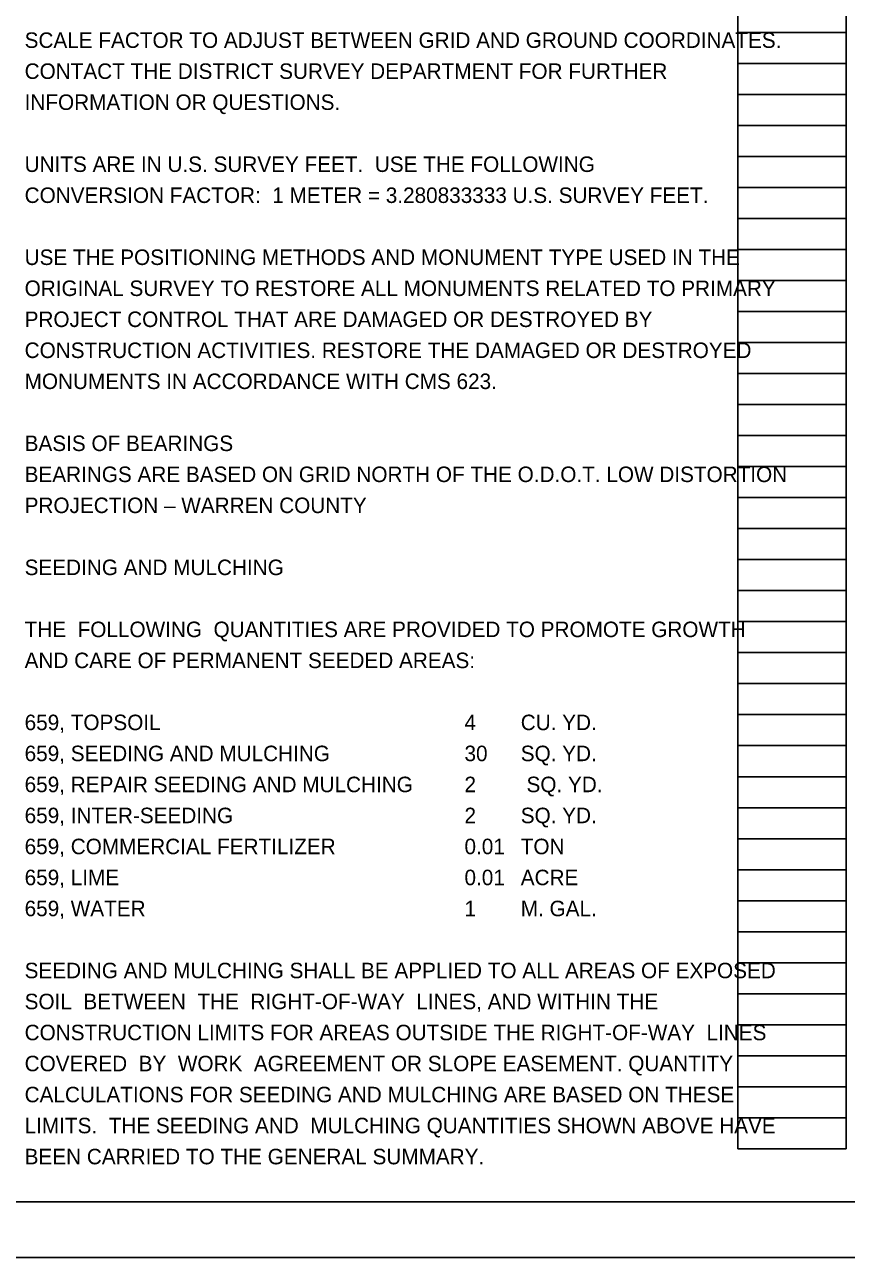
# Model space of a CAD drawing. Extents: x 0 to 34, y 0 to 22.
# Drawn here: x 17.24 to 24.66, y 0 to 11.13 of the extents above; entities that cross this region are included whole.
import ezdxf

# ---------------------------------------------------------------- set-up
doc = ezdxf.new("R2010")
doc.units = 0
for name, color, linetype in [('SH_Border', 7, 'Continuous'), ('SH_Cut_Line', 7, 'Continuous'), ('SH_Data', 7, 'Continuous'), ('SH_Text', 7, 'Continuous'), ('SN_P_Truss_Overhead', 7, 'Continuous')]:
    doc.layers.add(name, color=color, linetype=linetype)

msp = doc.modelspace()

# ---------------------------------------------------------------- linework, layer by layer
at = {"layer": 'SH_Border'}
msp.add_lwpolyline([(1.5, 21.5), (33.5, 21.5), (33.5, 0.5), (1.5, 0.5)], close=True, dxfattribs=at)
at = {"layer": 'SH_Cut_Line'}
msp.add_lwpolyline([(0, 0), (34, 0), (34, 22), (0, 22)], close=True, dxfattribs=at)
at = {"layer": 'SH_Data'}
for p, q in [((23.68, 0.98), (23.68, 21.14)), ((24.66, 0.98), (24.66, 21.14)), ((23.68, 11.06), (24.66, 11.06)), ((23.68, 10.78), (24.66, 10.78)), ((23.68, 10.5), (24.66, 10.5)), ((23.68, 10.22), (24.66, 10.22)), ((23.68, 9.94), (24.66, 9.94)), ((23.68, 9.66), (24.66, 9.66)), ((23.68, 9.38), (24.66, 9.38)), ((23.68, 9.1), (24.66, 9.1)), ((23.68, 8.82), (24.66, 8.82)), ((23.68, 8.54), (24.66, 8.54)), ((23.68, 8.26), (24.66, 8.26)), ((23.68, 7.98), (24.66, 7.98)), ((23.68, 7.7), (24.66, 7.7)), ((23.68, 7.42), (24.66, 7.42)), ((23.68, 7.14), (24.66, 7.14)), ((23.68, 6.86), (24.66, 6.86)), ((23.68, 6.58), (24.66, 6.58)), ((23.68, 6.3), (24.66, 6.3)), ((23.68, 6.02), (24.66, 6.02)), ((23.68, 5.74), (24.66, 5.74)), ((23.68, 5.46), (24.66, 5.46)), ((23.68, 5.18), (24.66, 5.18)), ((23.68, 4.9), (24.66, 4.9)), ((23.68, 4.62), (24.66, 4.62)), ((23.68, 4.34), (24.66, 4.34)), ((23.68, 4.06), (24.66, 4.06)), ((23.68, 3.78), (24.66, 3.78)), ((23.68, 3.5), (24.66, 3.5)), ((23.68, 3.22), (24.66, 3.22)), ((23.68, 2.94), (24.66, 2.94)), ((23.68, 2.66), (24.66, 2.66)), ((23.68, 2.38), (24.66, 2.38)), ((23.68, 2.1), (24.66, 2.1)), ((23.68, 1.82), (24.66, 1.82)), ((23.68, 1.54), (24.66, 1.54)), ((23.68, 1.26), (24.66, 1.26)), ((23.68, 0.98), (24.66, 0.98))]:
    msp.add_line(p, q, dxfattribs=at)

# ---------------------------------------------------------------- texts
at = {"layer": 'SH_Text'}
for s, p in [('SCALE FACTOR TO ADJUST BETWEEN GRID AND GROUND COORDINATES. ', (17.24, 10.92)), ('CONTACT THE DISTRICT SURVEY DEPARTMENT FOR FURTHER ', (17.24, 10.64)), ('INFORMATION OR QUESTIONS.', (17.24, 10.36)), ('UNITS ARE IN U.S. SURVEY FEET.  USE THE FOLLOWING', (17.24, 9.8)), ('CONVERSION FACTOR:  1 METER = 3.280833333 U.S. SURVEY FEET.', (17.24, 9.52)), ('USE THE POSITIONING METHODS AND MONUMENT TYPE USED IN THE ', (17.24, 8.96)), ('ORIGINAL SURVEY TO RESTORE ALL MONUMENTS RELATED TO PRIMARY ', (17.24, 8.68)), ('PROJECT CONTROL THAT ARE DAMAGED OR DESTROYED BY ', (17.24, 8.4)), ('CONSTRUCTION ACTIVITIES. RESTORE THE DAMAGED OR DESTROYED ', (17.24, 8.12)), ('MONUMENTS IN ACCORDANCE WITH CMS 623.', (17.24, 7.84)), ('BASIS OF BEARINGS', (17.24, 7.28)), ('BEARINGS ARE BASED ON GRID NORTH OF THE O.D.O.T. LOW DISTORTION ', (17.24, 7)), ('PROJECTION – WARREN COUNTY', (17.24, 6.72)), ('SEEDING AND MULCHING', (17.24, 6.16))]:
    msp.add_text(s, height=0.14, dxfattribs=at).set_placement(p)
at = {"layer": 'SN_P_Truss_Overhead'}
for s, p in [('THE  FOLLOWING  QUANTITIES ARE PROVIDED TO PROMOTE GROWTH ', (17.24, 5.6)), ('AND CARE OF PERMANENT SEEDED AREAS:', (17.24, 5.32)), ('659, TOPSOIL      ', (17.24, 4.76)), (' 4 ', (21.16, 4.76)), ('CU. YD.', (21.72, 4.76)), ('659, SEEDING AND MULCHING    ', (17.24, 4.48)), (' 30 ', (21.16, 4.48)), ('SQ. YD.', (21.72, 4.48)), ('659, REPAIR SEEDING AND MULCHING', (17.24, 4.2)), (' 2', (21.16, 4.2)), (' SQ. YD.', (21.72, 4.2)), ('659, INTER-SEEDING', (17.24, 3.92)), (' 2 ', (21.16, 3.92)), ('SQ. YD.', (21.72, 3.92)), ('659, COMMERCIAL FERTILIZER', (17.24, 3.64)), (' 0.01', (21.16, 3.64)), ('TON', (21.72, 3.64)), ('659, LIME', (17.24, 3.36)), (' 0.01', (21.16, 3.36)), ('ACRE', (21.72, 3.36)), ('659, WATER      ', (17.24, 3.08)), (' 1 ', (21.16, 3.08)), ('M. GAL.', (21.72, 3.08)), ('SEEDING AND MULCHING SHALL BE APPLIED TO ALL AREAS OF EXPOSED  ', (17.24, 2.52)), ('SOIL  BETWEEN  THE  RIGHT-OF-WAY  LINES, AND WITHIN THE ', (17.24, 2.24)), ('CONSTRUCTION LIMITS FOR AREAS OUTSIDE THE RIGHT-OF-WAY  LINES  ', (17.24, 1.96)), ('COVERED  BY  WORK  AGREEMENT OR SLOPE EASEMENT. QUANTITY ', (17.24, 1.68)), ('CALCULATIONS FOR SEEDING AND MULCHING ARE BASED ON THESE ', (17.24, 1.4)), ('LIMITS.  THE SEEDING AND  MULCHING QUANTITIES SHOWN ABOVE HAVE ', (17.24, 1.12)), ('BEEN CARRIED TO THE GENERAL SUMMARY.', (17.24, 0.84))]:
    msp.add_text(s, height=0.14, dxfattribs=at).set_placement(p)

doc.saveas('drawing.dxf')
